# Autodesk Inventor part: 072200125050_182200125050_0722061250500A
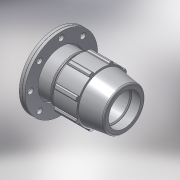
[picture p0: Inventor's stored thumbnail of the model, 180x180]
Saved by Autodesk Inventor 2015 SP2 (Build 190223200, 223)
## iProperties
Created: 2017-02
Part Number: 072200125050_182200125050_0722061250500A
Material: PVC-Piping
Description: PLASSON COMPRESSION FLANGE ADAPTOR 125-5"
Document SubType Name: Modeling
Designer: KIM
Mass: 92.6774 g
Surface Area: 199.44 cm^2
Volume: 66.1981 cm^3
Density: 1.4 g/cm^3
Appearance: Smooth - White
Author: KIM
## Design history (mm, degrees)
derived "07220.ipt"
feature "Solid1::07220.ipt"
tag "TaggingFeature1"
body "Solid1"
other parameters: "d2" = 125, "d4" = 38.57143, "d5" = 86.4, "d7" = 212, "d9" = 38.57143, "d11" = 7.71429, "d12" = 169.6, "d13" = 120 deg, "d14" = 162.5, "d15" = 8 deg, "d18" = 6.25, "d19" = 35 deg, "d20" = 17.5 deg, "d21" = 197.16, "d23" = 0, "d25" = 360 deg, "d27" = 4.24, "d42" = 94.5, "d43" = 6.36, "d46" = 3.75, "d53" = 2.5, "d67" = 10.6, "d73" = 22.5, "d74" = 90 deg, "d75" = 0.3, "d77" = 22, "d78" = 105, "d80" = 0, "d82" = 360 deg, "d85" = 180.2, "d86" = 169.6, "d87" = 1.25, "d93" = 13.5, "d94" = 125, "d95" = 112.5, "d96" = 0.3, "d99" = 360 deg, "d_" = 125, "E_" = 212, "S_" = 22, "DN_" = 125
